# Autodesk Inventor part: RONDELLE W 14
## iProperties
Created: 2004-11
Part Number: RONDELLE W 14
Document SubType Name: Modeling
Designer: Bruno
Manufacturer: Standard
Standards Organization: Custom
Author: Bruno
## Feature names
1. Base1
